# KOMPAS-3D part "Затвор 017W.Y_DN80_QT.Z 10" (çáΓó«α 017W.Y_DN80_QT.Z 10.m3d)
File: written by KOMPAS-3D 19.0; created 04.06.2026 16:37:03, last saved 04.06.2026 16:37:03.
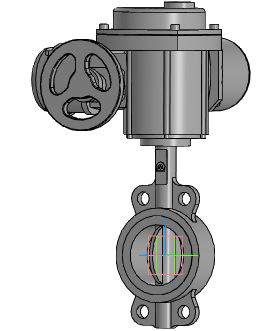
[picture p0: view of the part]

Document properties: Автор: Энергия; Полное имя файла: ..\..\..\3d для проектировщиков\017W разные\x.x Тип 017W.Y(S) Затвор дисковый поворотный межфланцевый\Затвор 017W.Y(S)_DN32-DN450_QT.Z\Затвор 017W.Y_DN80_QT.Z 10.a3d

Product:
- Part/product: Затвор 017W.Y_DN80_QT.Z 10
    Масса: 31.7243

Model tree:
1. Операция без истории:1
